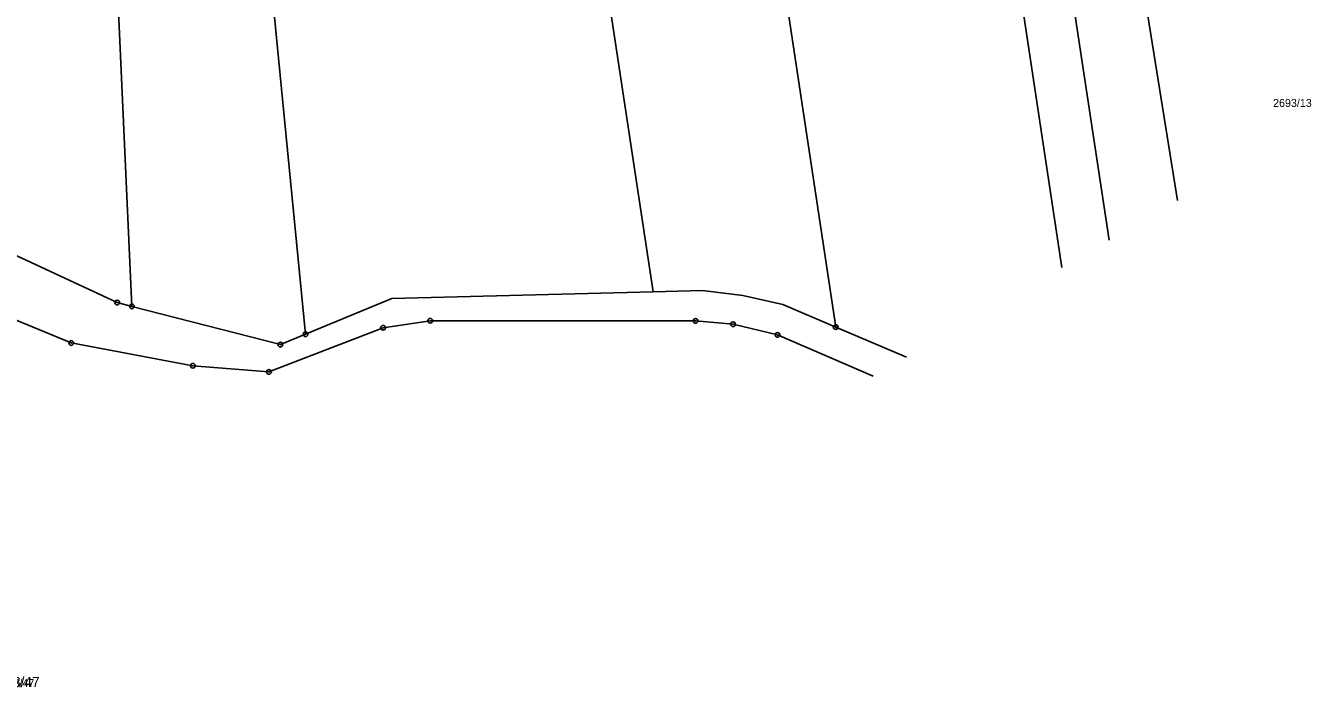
# Model space of a CAD drawing. Extents: x -758836 to -757729, y -1175316 to -1174366.
# Drawn here: x -758099.5 to -757826.5, y -1175005.1 to -1174864.5 of the extents above; entities that cross this region are included whole.
import ezdxf

# ---------------------------------------------------------------- set-up
doc = ezdxf.new("R2010")
doc.units = 0
for name, color, linetype in [('Hranice parcel', 7, 'Continuous'), ('Parcelní čísla', 7, 'Continuous'), ('Značky bodu BP', 7, 'Continuous')]:
    doc.layers.add(name, color=color, linetype=linetype)

msp = doc.modelspace()

# ---------------------------------------------------------------- linework, layer by layer
at = {"layer": 'Hranice parcel'}
for p, q in [((-757966.21, -1174921.06), (-757991.64, -1174752.6)), ((-758056.09, -1174765.35), (-758040.03, -1174930.09)), ((-758076.9, -1174924.17), (-758083.84, -1174772.54)), ((-757927.46, -1174928.58), (-757912.42, -1174934.95))]:
    msp.add_line(p, q, dxfattribs=at)
for points in [[(-757854.84, -1174901.71), (-757869.41, -1174811.27), (-757893.96, -1174658.87)], [(-757905.12, -1174673.47), (-757883.79, -1174814.77), (-757869.4, -1174910.11)], [(-757879.43, -1174915.9), (-757894.52, -1174815.94), (-757914.95, -1174680.62)], [(-757959.61, -1174715.65), (-757943.53, -1174822.15), (-757927.46, -1174928.58)], [(-758114.13, -1174910.8), (-758107.54, -1174910.58), (-758080.03, -1174923.36), (-758076.9, -1174924.17)], [(-757919.47, -1174939.02), (-757939.8, -1174930.25), (-757949.26, -1174927.98), (-757957.21, -1174927.28), (-758013.54, -1174927.25), (-758023.59, -1174928.73), (-758047.8, -1174938.11), (-758063.96, -1174936.81), (-758089.79, -1174931.96), (-758110.46, -1174923.41), (-758137.06, -1174918.45)], [(-758040.03, -1174930.09), (-758021.7, -1174922.52), (-757966.21, -1174921.06)], [(-757966.21, -1174921.06), (-757955.71, -1174920.78), (-757947.16, -1174921.89), (-757938.71, -1174923.81), (-757927.46, -1174928.58)], [(-758076.9, -1174924.17), (-758045.39, -1174932.31), (-758040.03, -1174930.09)]]:
    msp.add_lwpolyline(points, dxfattribs=at)
at = {"layer": 'Značky bodu BP'}
for centre, radius in [((-758080.03, -1174923.36), 0.5), ((-758080.03, -1174923.36), 0.0303), ((-758076.9, -1174924.17), 0.5), ((-758076.9, -1174924.17), 0.0303), ((-758013.54, -1174927.25), 0.5), ((-758013.54, -1174927.25), 0.0303), ((-757957.21, -1174927.28), 0.5), ((-757957.21, -1174927.28), 0.0303), ((-757949.26, -1174927.98), 0.5), ((-758040.03, -1174930.09), 0.5), ((-758040.03, -1174930.09), 0.0303), ((-758023.59, -1174928.73), 0.5), ((-758023.59, -1174928.73), 0.0303), ((-757949.26, -1174927.98), 0.0303), ((-757939.8, -1174930.25), 0.5), ((-757939.8, -1174930.25), 0.0303), ((-757927.46, -1174928.58), 0.5), ((-757927.46, -1174928.58), 0.0303), ((-758089.79, -1174931.96), 0.5), ((-758089.79, -1174931.96), 0.0303), ((-758045.39, -1174932.31), 0.5), ((-758045.39, -1174932.31), 0.0303), ((-758063.96, -1174936.81), 0.5), ((-758063.96, -1174936.81), 0.0303), ((-758047.8, -1174938.11), 0.5), ((-758047.8, -1174938.11), 0.0303)]:
    msp.add_circle(centre, radius, dxfattribs=at)

# ---------------------------------------------------------------- texts
at = {"layer": 'Parcelní čísla'}
for s, height, p in [('2693/13', 1.7, (-757834.58, -1174881.81)), ('2678/47', 2.175, (-758107.02, -1175005.08)), ('2678/47', 1.7, (-758105.86, -1175005.08))]:
    msp.add_text(s, height=height, dxfattribs=at).set_placement(p)

doc.saveas('drawing.dxf')
